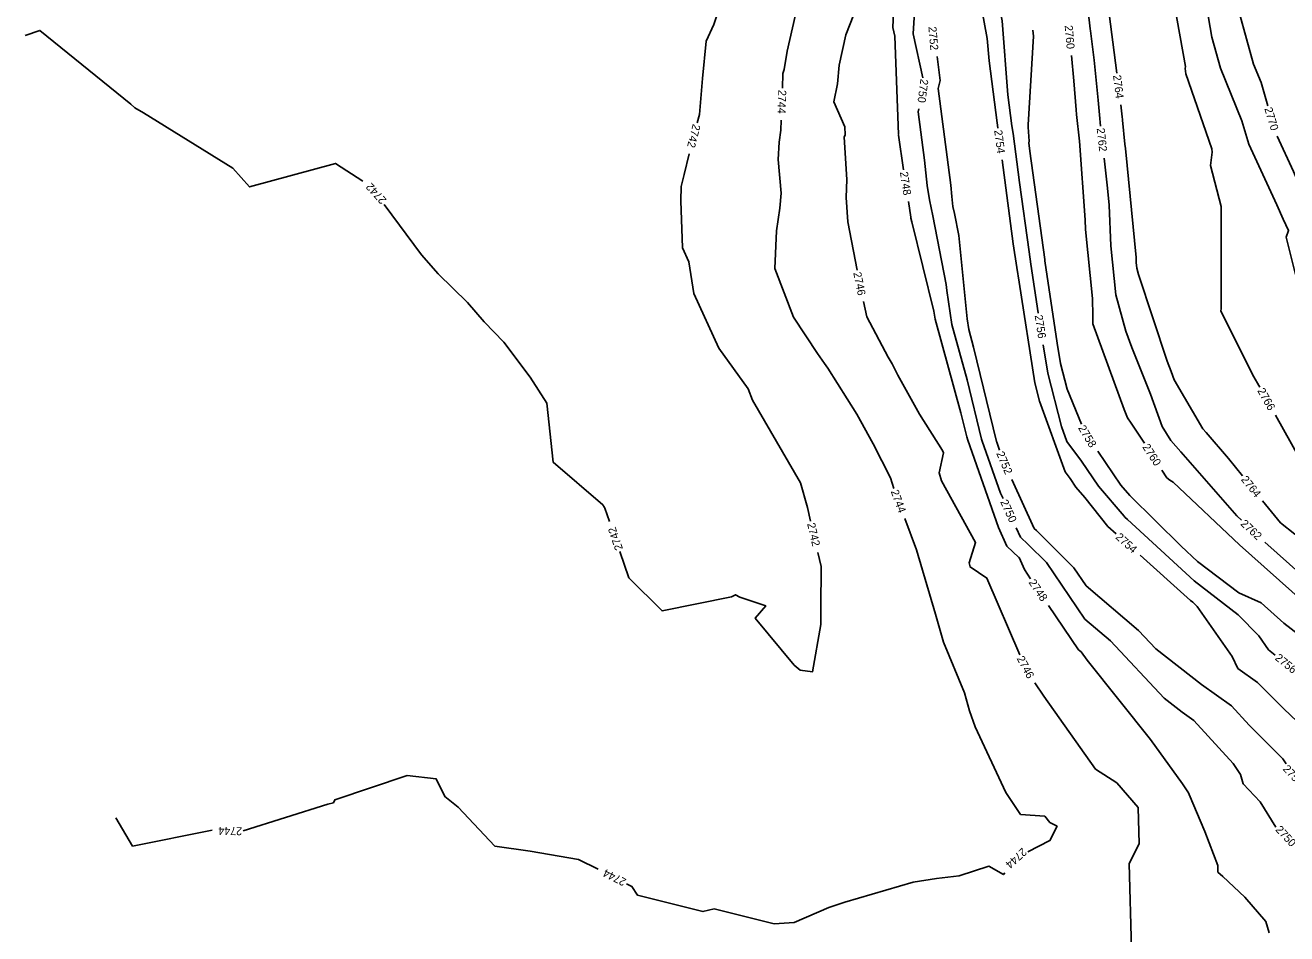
# Model space of a CAD drawing. Extents: x 1326424 to 1329294, y 1001359 to 1003823.
# Drawn here: x 1327963.9 to 1328279.2, y 1001682.9 to 1001910 of the extents above; entities that cross this region are included whole.
import ezdxf

# ---------------------------------------------------------------- set-up
doc = ezdxf.new("R2010")
doc.units = 0
doc.layers.add('Prop Rem of Exist Asph Pvmt', color=7, linetype='Continuous')
doc.layers.add('Scratch_Level_3', color=7, linetype='Continuous')

msp = doc.modelspace()

# ---------------------------------------------------------------- linework, layer by layer
at = {"layer": 'Prop Rem of Exist Asph Pvmt'}
for points in [[(1328225.4, 1001902.49), (1328226.06, 1001896.17), (1328226.6, 1001888.91), (1328226.72, 1001887.7), (1328227.47, 1001881.08), (1328228.82, 1001861.39), (1328228.92, 1001858.99), (1328230.68, 1001841.68), (1328230.78, 1001837.37), (1328230.78, 1001835.38), (1328238.6, 1001814), (1328239.47, 1001811.92), (1328240.37, 1001810.6), (1328243.66, 1001805.54)], [(1328248.02, 1001798.84), (1328249.27, 1001796.93), (1328249.99, 1001796.31), (1328250.81, 1001795.82), (1328267.44, 1001780.12), (1328283.61, 1001765.72), (1328287.06, 1001762.63), (1328293.33, 1001757.94), (1328295.84, 1001755.96), (1328311.94, 1001743.9), (1328318.02, 1001740.2), (1328321.32, 1001738.05), (1328324.86, 1001735.33)]]:
    msp.add_lwpolyline(points, dxfattribs=at)
at = {"layer": 'Scratch_Level_3'}
for points in [[(1328245.68, 1001995.16), (1328245.7, 1001994.85), (1328243.02, 1001971.36), (1328241.09, 1001961.35), (1328239.3, 1001956.25), (1328240.96, 1001948.53), (1328235.58, 1001940.44), (1328235.48, 1001937.06), (1328236.16, 1001931.91), (1328234.11, 1001923.31), (1328234.2, 1001918.36), (1328234.29, 1001917.54), (1328234.55, 1001915.49), (1328236.75, 1001898.05)], [(1328155.23, 1001990.21), (1328154.6, 1001987.02), (1328154.35, 1001975.32), (1328149.89, 1001958.8), (1328148.61, 1001948.25), (1328147.22, 1001940.6), (1328149.43, 1001934.44), (1328149.94, 1001933.31), (1328151.1, 1001930.24), (1328153.85, 1001925.97), (1328154.93, 1001924.39), (1328155.57, 1001923.75), (1328157.44, 1001921.19), (1328157.54, 1001919.51), (1328157.4, 1001916.47), (1328157.05, 1001915.21), (1328154.39, 1001903.52), (1328153.63, 1001898.94), (1328153.3, 1001897.95), (1328153.18, 1001894.26)], [(1328183.42, 1001991.7), (1328183.4, 1001991.54), (1328183.19, 1001986.38), (1328180.96, 1001978.22), (1328184.05, 1001975.39), (1328184.54, 1001975.18), (1328186.23, 1001973.25), (1328190.02, 1001969.75), (1328186.31, 1001955.8), (1328186.08, 1001955.02), (1328185.85, 1001954.08), (1328185.85, 1001953.48), (1328186.52, 1001940.09), (1328185.71, 1001934.68), (1328185.71, 1001934.37), (1328186.4, 1001922.79), (1328186.5, 1001918.72), (1328185.86, 1001907.89), (1328188.31, 1001896.91)], [(1328266.39, 1001988.57), (1328266.56, 1001985.95), (1328265.19, 1001973.96), (1328266.21, 1001958.16), (1328266.25, 1001956.58), (1328268.05, 1001944.6), (1328267.89, 1001938.34), (1328267.49, 1001920.48), (1328267.52, 1001915.06), (1328267.44, 1001912.99), (1328270.95, 1001900.29), (1328272.81, 1001895.72), (1328274.5, 1001889.91)], [(1328131.98, 1001984.04), (1328132.78, 1001976.4), (1328132.67, 1001963.36), (1328131.37, 1001953.08), (1328132.76, 1001934.46), (1328132.95, 1001932.22), (1328133.72, 1001921.03), (1328133.94, 1001920.94), (1328134.34, 1001919.9), (1328136.19, 1001914.65), (1328136.68, 1001913.73), (1328136.89, 1001912.67), (1328136.01, 1001910.21), (1328134.17, 1001906.03), (1328133.24, 1001896.68), (1328132.44, 1001887.75), (1328131.89, 1001885.62)], [(1328205.52, 1001982.67), (1328204.92, 1001979.57), (1328200.81, 1001967.85), (1328200.78, 1001967.73), (1328199.45, 1001961.58), (1328199.4, 1001959.2), (1328198.32, 1001943.6), (1328199.62, 1001936.53), (1328199.93, 1001933.15), (1328200.12, 1001929.9), (1328204.4, 1001906.75), (1328204.83, 1001901.14), (1328206.87, 1001885.6), (1328206.95, 1001885.01), (1328207.05, 1001884.3)], [(1328236.9, 1001981.66), (1328236.66, 1001979.52), (1328233.85, 1001964.99), (1328231.26, 1001957.59), (1328232.57, 1001951.51), (1328227.16, 1001943.37), (1328226.71, 1001940.2), (1328228.29, 1001936.93), (1328228.39, 1001935.84), (1328228.64, 1001922.43), (1328230.11, 1001909.13), (1328230.17, 1001908.61), (1328231.09, 1001901.31), (1328232.13, 1001891.33), (1328232.41, 1001887.59), (1328232.68, 1001884.78)], [(1328173.37, 1001967.73), (1328171.46, 1001960.43), (1328175.76, 1001959.21), (1328176.55, 1001958.54), (1328178.08, 1001957.04), (1328181.89, 1001952.17), (1328180.95, 1001948.29), (1328180.94, 1001938.02), (1328181.1, 1001934.74), (1328180.9, 1001933.41), (1328180.91, 1001933.34), (1328181.14, 1001929.41), (1328180.89, 1001911.41), (1328180.77, 1001909.5), (1328181.27, 1001907.28), (1328182.17, 1001882.71), (1328182.15, 1001882.64), (1328182.17, 1001882.56), (1328182.17, 1001882.51), (1328183.48, 1001873.86)], [(1328164.01, 1001944), (1328164.86, 1001942.48), (1328165.22, 1001941.72), (1328166.25, 1001940.37), (1328171.13, 1001933.01), (1328171.6, 1001932.57), (1328173.71, 1001928.76), (1328173.84, 1001927.48), (1328173.23, 1001923.44), (1328173.15, 1001921.26), (1328172.25, 1001915.92), (1328171.01, 1001912.75), (1328169.01, 1001907.66), (1328167.39, 1001900.03), (1328166.98, 1001895.4), (1328166.01, 1001890.85), (1328168.75, 1001884.65), (1328168.87, 1001882.65), (1328168.64, 1001882.02), (1328169.26, 1001871.44), (1328169.13, 1001866.98), (1328169.57, 1001860.85), (1328171.86, 1001848.78)], [(1328256.51, 1001943.27), (1328256.62, 1001938.92), (1328258.24, 1001920.25), (1328260.54, 1001907.05), (1328262.68, 1001899.33), (1328268.03, 1001886.16), (1328269.74, 1001880.27), (1328276.76, 1001865.11), (1328278.3, 1001861.57), (1328279.69, 1001858.71), (1328279.07, 1001857.02), (1328281.43, 1001847.71)], [(1328205.15, 1001937.26), (1328205.71, 1001931.13), (1328206.37, 1001920.43), (1328208.09, 1001911.1), (1328209.54, 1001892.6), (1328210.54, 1001884.92), (1328210.82, 1001882.95), (1328212.42, 1001870.72), (1328214.82, 1001853.41), (1328215.31, 1001850.31), (1328217.12, 1001838.16), (1328217.14, 1001838.05)], [(1328251.12, 1001915.46), (1328253.96, 1001899.75), (1328253.86, 1001899.21), (1328254.03, 1001897.86), (1328260.51, 1001879.12), (1328260.56, 1001878.28), (1328260.15, 1001874.93), (1328262.83, 1001864.75), (1328262.84, 1001839.23), (1328262.75, 1001838.53), (1328271.02, 1001822.16), (1328272.23, 1001819.99), (1328272.48, 1001819.55)], [(1328048.3, 1001871.03), (1328041.47, 1001875.47), (1328019.97, 1001869.6), (1328015.86, 1001874.3), (1327993.5, 1001888.15), (1327991.34, 1001889.4), (1327990.36, 1001890.31), (1327967.61, 1001908.75), (1327963.94, 1001907.45)], [(1328215.78, 1001908.79), (1328215.92, 1001907.28), (1328214.6, 1001885.11), (1328214.57, 1001884.51), (1328214.82, 1001881.07), (1328214.8, 1001880.64), (1328215, 1001878.56), (1328218.76, 1001851.48), (1328218.81, 1001851.16), (1328221.89, 1001830.54), (1328222.68, 1001825.49), (1328224.34, 1001819.03), (1328227.95, 1001810.34)], [(1328191.83, 1001902.23), (1328192.61, 1001896.22), (1328192.12, 1001894.18), (1328195.28, 1001870.06), (1328195.57, 1001867.2), (1328195.81, 1001864.75), (1328196.19, 1001862.96), (1328197.27, 1001857.5), (1328199.34, 1001836.68), (1328199.75, 1001833.97), (1328200.96, 1001829.55), (1328206.71, 1001805.95), (1328206.76, 1001805.78), (1328207.45, 1001803.83)], [(1328187.31, 1001889.11), (1328187.14, 1001888.41), (1328188.72, 1001876.31), (1328189.36, 1001870), (1328189.92, 1001866.36), (1328190.75, 1001862.4), (1328194.14, 1001845.26), (1328194.29, 1001843.74), (1328195.57, 1001835.24), (1328199.38, 1001821.35), (1328202.98, 1001806.56), (1328203.12, 1001806.04), (1328207.71, 1001793.05), (1328208.32, 1001791.71)], [(1328237.75, 1001890.11), (1328238.13, 1001887.12), (1328238.19, 1001886.5), (1328238.21, 1001886.27), (1328238.79, 1001880.31), (1328238.91, 1001879.24), (1328241.59, 1001851.95), (1328241.64, 1001850.75), (1328241.79, 1001849.3), (1328242.22, 1001847.74), (1328249.35, 1001826.04), (1328250.37, 1001823.49), (1328251.12, 1001821.4), (1328258.28, 1001809.18), (1328259.06, 1001808.26), (1328264.71, 1001801.69), (1328268.18, 1001797.39)], [(1328152.91, 1001886.27), (1328152.83, 1001883.77), (1328152.34, 1001880.78), (1328152.1, 1001876.5), (1328152.86, 1001868.08), (1328152.57, 1001864.26), (1328151.72, 1001858.61), (1328151.3, 1001849.26), (1328155.93, 1001837.02), (1328161.99, 1001827.95), (1328163.72, 1001825.48), (1328164.57, 1001824.32), (1328171.78, 1001812.77), (1328175.89, 1001805.4), (1328180.23, 1001796.86), (1328181.03, 1001794.24)], [(1328276.83, 1001882.27), (1328280.9, 1001873.46), (1328284.68, 1001864.82), (1328288.06, 1001857.84), (1328286.54, 1001853.71), (1328290.49, 1001838.16), (1328289.01, 1001833.14), (1328289.36, 1001832.13), (1328293.99, 1001822.12), (1328294.99, 1001815.76), (1328298.14, 1001792.36), (1328302.27, 1001789.05)], [(1328129.91, 1001877.87), (1328128.59, 1001872.69), (1328127.92, 1001869.73), (1328127.81, 1001866.13), (1328128.24, 1001854.36), (1328129.77, 1001850.87), (1328131.04, 1001842.93), (1328137.27, 1001829.33), (1328144.66, 1001819.13), (1328145.68, 1001816.3), (1328157.7, 1001795.62), (1328159.43, 1001789.47), (1328160.23, 1001786.04)], [(1328208.09, 1001876.37), (1328210.17, 1001860.43), (1328210.88, 1001855.35), (1328211.8, 1001849.46), (1328212.36, 1001845.77), (1328216.3, 1001820.68), (1328217.48, 1001816.07), (1328223.82, 1001798.43), (1328225.09, 1001796.73), (1328226.55, 1001794.58), (1328228.76, 1001791.99), (1328234.54, 1001784.76), (1328236.64, 1001782.88)], [(1328233.57, 1001876.83), (1328234.44, 1001869.27), (1328234.85, 1001865.03), (1328235.28, 1001854.87), (1328236.52, 1001842.67), (1328239.04, 1001833.55), (1328240.52, 1001829.5), (1328245.2, 1001817.8), (1328248.12, 1001809.69), (1328250.26, 1001806.26), (1328252.78, 1001803.37), (1328266.76, 1001787.36), (1328267.9, 1001786.28)], [(1328109.96, 1001786.02), (1328108.84, 1001789.28), (1328108.71, 1001789.5), (1328108.28, 1001790.17), (1328095.92, 1001800.78), (1328094.29, 1001815.6), (1328090.11, 1001822.09), (1328083.59, 1001830.78), (1328078.67, 1001835.92), (1328074.5, 1001840.7), (1328067.13, 1001847.91), (1328062.98, 1001852.65), (1328053.63, 1001865.19)], [(1328184.67, 1001865.95), (1328185.27, 1001862.01), (1328185.31, 1001861.83), (1328185.49, 1001860.92), (1328191.07, 1001838.58), (1328191.38, 1001836.52), (1328197.8, 1001813.16), (1328199.26, 1001807.17), (1328199.49, 1001806.31), (1328207.21, 1001784.45), (1328209.31, 1001779.8), (1328212.31, 1001776.99), (1328212.33, 1001776.96), (1328213.65, 1001774), (1328215.23, 1001771.65)], [(1328173.47, 1001840.94), (1328174.3, 1001837.15), (1328179.65, 1001827.09), (1328180.59, 1001825.4), (1328182.06, 1001822.56), (1328187.47, 1001812.83), (1328193.17, 1001803.69), (1328193.43, 1001803.11), (1328192.39, 1001798.16), (1328192.96, 1001796.18), (1328201.48, 1001780.73), (1328199.82, 1001775.61), (1328200.11, 1001774.64), (1328204.28, 1001771.82), (1328212.53, 1001752.67)], [(1328218.38, 1001830.15), (1328219.49, 1001823.09), (1328222.92, 1001809.75), (1328224.28, 1001805.94), (1328227.96, 1001801.03), (1328232.16, 1001794.83), (1328238.56, 1001787.35), (1328238.76, 1001787.1), (1328239.44, 1001786.48), (1328256.08, 1001771.12), (1328267.09, 1001762.67), (1328272.28, 1001757.43), (1328274.68, 1001753.89), (1328276.38, 1001752.57)], [(1328276.4, 1001812.58), (1328282.45, 1001801.85), (1328284.2, 1001788.82), (1328284.94, 1001788.23), (1328291.91, 1001782.94), (1328293.93, 1001780.44), (1328299.06, 1001773.5), (1328304.57, 1001768.05), (1328308.29, 1001765.71), (1328310, 1001764.76), (1328319.51, 1001761.64), (1328330.85, 1001757.09), (1328341.9, 1001749.8), (1328345.06, 1001748.45)], [(1328232.05, 1001803.52), (1328237.77, 1001795.08), (1328240, 1001792.46), (1328252.86, 1001779.78), (1328256.95, 1001776.01), (1328267.23, 1001768.12), (1328272.82, 1001765.66), (1328278.52, 1001760.58), (1328290.98, 1001750.88), (1328293.2, 1001749.23), (1328300.46, 1001743.81), (1328307.11, 1001738.64)], [(1328210.56, 1001796.47), (1328216.08, 1001784.27), (1328216.69, 1001783.7), (1328226.04, 1001774.43), (1328229.1, 1001769.94), (1328242.21, 1001758.7), (1328246.48, 1001754.15), (1328257.93, 1001745.23), (1328265.43, 1001739.87), (1328269.8, 1001735.1), (1328278.24, 1001726.69), (1328279.07, 1001725.38)], [(1328273.2, 1001791.16), (1328277.68, 1001785.61), (1328281.23, 1001782.82), (1328292.04, 1001771.67), (1328293.19, 1001770.12), (1328294.97, 1001768.35), (1328304.09, 1001761.05), (1328318.09, 1001754.76), (1328320.51, 1001753.97), (1328321.74, 1001753.47), (1328341.21, 1001740.63), (1328341.48, 1001740.51), (1328353.32, 1001733.3)], [(1328183.79, 1001786.73), (1328186.69, 1001778.88), (1328191.45, 1001762.85), (1328193.44, 1001755.82), (1328198.69, 1001743.19), (1328199.91, 1001738.67), (1328201.36, 1001734.66), (1328209.06, 1001718.22), (1328212.71, 1001712.78), (1328218.76, 1001712.33), (1328220.05, 1001710.77), (1328221.82, 1001709.81), (1328220.06, 1001706.24), (1328214.54, 1001703.44)], [(1328211.62, 1001784.42), (1328212.7, 1001782.03), (1328214.62, 1001780.24), (1328219.19, 1001775.7), (1328228.79, 1001761.6), (1328235.17, 1001756.13), (1328248.59, 1001741.84), (1328253.1, 1001738.33), (1328256.04, 1001736.22), (1328265.85, 1001725.52), (1328267.7, 1001722.73), (1328268.36, 1001720.37), (1328272.55, 1001715.89), (1328276.53, 1001709.58)], [(1328162.06, 1001778.25), (1328162.88, 1001774.72), (1328162.8, 1001764.35), (1328162.82, 1001762.36), (1328162.77, 1001760.25), (1328160.73, 1001748.43), (1328157.66, 1001748.8), (1328156.12, 1001750.08), (1328146.38, 1001761.79), (1328149.01, 1001764.9), (1328142.58, 1001767.07), (1328141.44, 1001767.66), (1328140.48, 1001767.17), (1328123.11, 1001763.65), (1328114.8, 1001771.89), (1328112.55, 1001778.45)], [(1328273.76, 1001780.84), (1328276.85, 1001778.09), (1328289.9, 1001766.4), (1328292.79, 1001764.24), (1328298.9, 1001759.43), (1328301.36, 1001757.46), (1328304.94, 1001755.85), (1328319.41, 1001747.03), (1328331.44, 1001739.19), (1328335.53, 1001736.06), (1328340.71, 1001732.36), (1328351.2, 1001725.96), (1328354.67, 1001722.67)], [(1328242.6, 1001777.54), (1328254.37, 1001767), (1328255.2, 1001766.23), (1328255.75, 1001765.8), (1328256.83, 1001764.72), (1328265.57, 1001752.25), (1328267, 1001749.27), (1328271.93, 1001745.74), (1328278.52, 1001739.16), (1328285.27, 1001732.78), (1328291.51, 1001728.18), (1328298.66, 1001721.73), (1328313.73, 1001711.34), (1328315.28, 1001710.14)], [(1328219.69, 1001765.01), (1328227.16, 1001753.91), (1328227.83, 1001753.37), (1328229.35, 1001751.36), (1328245.16, 1001731.45), (1328253.21, 1001720.42), (1328254.71, 1001718.15), (1328254.83, 1001717.72), (1328258.78, 1001708.49), (1328262.03, 1001700.01), (1328262.05, 1001698.33), (1328263.22, 1001697.27), (1328268.78, 1001692.11), (1328274.04, 1001686.02), (1328274.8, 1001683.14)], [(1328216.26, 1001745.62), (1328218.56, 1001742.29), (1328231.47, 1001724.09), (1328236.76, 1001720.67), (1328242.12, 1001714.52), (1328242.37, 1001705.38), (1328239.81, 1001700.48), (1328240.45, 1001679.02), (1328239.7, 1001674.6), (1328241.2, 1001662.59), (1328235.05, 1001660.66)], [(1328107.11, 1001699.04), (1328102.23, 1001701.5), (1328090.11, 1001703.59), (1328081.28, 1001704.85), (1328072.15, 1001714.59), (1328068.8, 1001717.23), (1328066.66, 1001721.62), (1328059.38, 1001722.51), (1328041.35, 1001716.44), (1328040.96, 1001715.7), (1328039.55, 1001715.35), (1328018.4, 1001708.7)], [(1328010.67, 1001708.86), (1327990.79, 1001704.83), (1327986.59, 1001711.94)], [(1328208.79, 1001698.18), (1328208.44, 1001697.71), (1328204.8, 1001699.87), (1328197.35, 1001697.42), (1328191.66, 1001696.73), (1328185.86, 1001695.87), (1328168.79, 1001690.81), (1328164.78, 1001689.52), (1328156.14, 1001685.75), (1328151.16, 1001685.44), (1328136.16, 1001689.14), (1328133.33, 1001688.47), (1328116.95, 1001692.6), (1328115.57, 1001694.78), (1328114.25, 1001695.44)]]:
    msp.add_lwpolyline(points, dxfattribs=at)

# ---------------------------------------------------------------- texts
at = {"layer": 'Prop Rem of Exist Asph Pvmt'}
for rotation, p in [(275.0926, (1328223.73, 1001909.94)), (303.0724, (1328243.06, 1001804.63))]:
    msp.add_text('2760', height=2, rotation=rotation, dxfattribs=at).set_placement(p)
at = {"layer": 'Scratch_Level_3'}
for s, rotation, p in [('2752', 274.9738, (1328189.67, 1001909.62)), ('2764', 277.1926, (1328235.81, 1001897.49)), ('2750', 262.6939, (1328187.7, 1001896.68)), ('2744', 268.0767, (1328152.17, 1001893.88)), ('2770', 286.9688, (1328273.61, 1001889.2)), ('2742', 255.6666, (1328130.82, 1001885.46)), ('2754', 277.4658, (1328206.11, 1001883.75)), ('2762', 276.4215, (1328231.73, 1001884.24)), ('2748', 278.5978, (1328182.55, 1001873.3)), ('2742', 132.3839, (1328054.39, 1001866.43)), ('2746', 281.642, (1328170.88, 1001848.15)), ('2756', 278.9247, (1328216.22, 1001837.48)), ('2766', 299.3884, (1328271.82, 1001818.68)), ('2758', 300.9927, (1328227.03, 1001809.34)), ('2752', 292.9258, (1328206.6, 1001803.02)), ('2764', 308.8895, (1328267.68, 1001796.43)), ('2744', 290.1572, (1328180.23, 1001793.5)), ('2750', 294.3473, (1328207.58, 1001790.92)), ('2742', 108.9282, (1328113.36, 1001779.17)), ('2742', 283.1812, (1328159.35, 1001785.41)), ('2762', 317.1098, (1328267.52, 1001785.23)), ('2754', 318.1429, (1328236.29, 1001781.85)), ('2748', 303.922, (1328214.63, 1001770.74)), ('2756', 320.8385, (1328276.13, 1001751.59)), ('2746', 297.8769, (1328211.68, 1001751.76)), ('2752', 313.0358, (1328278.12, 1001724.02)), ('2744', 178.8335, (1328018.16, 1001709.54)), ('2750', 312.9663, (1328276.27, 1001708.84)), ('2744', 222.5073, (1328213.15, 1001704.54)), ('2744', 153.2467, (1328114.33, 1001696.52))]:
    msp.add_text(s, height=2, rotation=rotation, dxfattribs=at).set_placement(p)

doc.saveas('drawing.dxf')
